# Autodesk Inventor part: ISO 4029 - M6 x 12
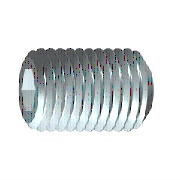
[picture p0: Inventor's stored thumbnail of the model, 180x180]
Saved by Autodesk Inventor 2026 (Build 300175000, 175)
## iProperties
IsCustomPart: 1
Created: 2021-02
Part Number: ISO 4029 - M6 x 12
Material: Stainless Steel, 440C
Description: Hexagon socket set screw with cup point
Document SubType Name: Modeling
Standard: ISO 4029
Designer: Lars Bertram Pedersen
Standard Revision: Third edition 2003-12-01
Standards Organization: ISO
Language: en-US
Size Designation: M6 x 12
Categories: <MemberInstance><Categories><Category DisplayName="Fasteners" InternalName="e4da775c-781d-43d5-af7c-5136215cf5a6" Mnemonic="FSTN"><Category DisplayName="Bolts"
Density: 7.75 g/cm^3
Appearance: Semi-Polished
Author: Lars Bertram Pedersen
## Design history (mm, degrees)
revolve "Body" stored, may be unused: angle "d6" = 90 deg
sketch "Sketch2"
  geometry: L1 (1.732, 0)-(0.866, -1.5); L2 (0.866, -1.5)-(-0.866, -1.5); L3 (-0.866, -1.5)-(-1.732, 0); L4 (-1.732, 0)-(-0.866, 1.5); L5 (-0.866, 1.5)-(0.866, 1.5); L6 (0.866, 1.5)-(1.732, 0); C1 r 3 at (0, 0) reference; A1 r 1.732 centre (0, 0) between (1.732, 0) and (0.866, -1.5) reference; 1 further point
  constraints: 12 end point, 2 point on circle, 1 coincident, 1 horizontal, 11 other
extrude "Slot" join sketch "Sketch2" distance "d8" = 3.5 (= INTI); taper "d9" = 0 deg
workaxis "Work Axis1"
workplane "Work Plane1"
body "Solid1"
chamfer "Chamfer1" distance "d10" = 1.5 (= -0.5 x SPD + 0.5 x NND); stored, may be unused: angle "d11" = 45 deg (= FAWI), second distance "d33" = 1.5 (= -0.5 x SPD + 0.5 x NND)
feature "Thread" dims "d14" = 12 (= NLG), "d15" = 0
chamfer "Chamfer2" distance "d12" = 0.61345 (= -0.5 x GD1 + 0.5 x NND); stored, may be unused: angle "d13" = 45 deg (= FAWI), second distance "d34" = 0.61345 (= -0.5 x GD1 + 0.5 x NND)
sketch "Sketch1"
  geometry: L1 (0.866, 0)-(7.5, 0); L2 (12, 1.732)-(12, 3); L3 (12, 3)-(0, 3); L4 (12, 1.732)-(8.5, 1.732); L5 (8.5, 1.732)-(7.5, 0); L6 (0, 1.5)-(0.866, 0); L7 (0, -0.6)-(0, 3.6) reference; L8 (0, 1.5)-(0, 3); 1 further point
  constraints: 14 end point, 2 parallel, 2 perpendicular, 1 horizontal, 1 midpoint, 1 point on line
  dimensions: "d0" = 3.5 distance of L2.start L4.end (= INTI); "d1" = 60 deg angle of L5 L1; "d2" = 6 diameter of L3 L1 (= NND); "d3" = 3.4641 diameter of L4 L1 (= 1.1547 x SW); "d4" = 12 distance from line of L2 L6.start (= NLG); "d5" = 60 deg angle of L1 L6 (= 0.5 x ANG); "d7" = 3 diameter of L6.start L1 (= SPD)
other parameters: "NND" = 6 [user parameter; used in 5 equation terms], "NLG" = 12 [user parameter; used in 2 equation terms], "INTI" = 3.5 [user parameter; used in 2 equation terms], "FAWI" = 45 deg [user parameter; used in 2 equation terms], "SW" = 3 [user parameter; used in 2 equation terms], "GD1" = 4.7731 (= THREADDIA - 1.2269 x PTC) [user parameter; used in 2 equation terms], "ANG" = 120 deg [user parameter; used in 1 equation term], "FAWI1" = 45 deg [user parameter], "SPD" = 3 [user parameter; used in 3 equation terms], "d16" = 0, "d35" = 0, "d37" = 0, "GUL" = 0.61345 (= 0.61345 x PTC) [user parameter], "TOA" = 30 deg [user parameter], "THREADDIA" = 6 [user parameter; used in 1 equation term], "PTC" = 1 [user parameter; used in 4 equation terms], "GAL" = 0.61345 (= 0.61345 x PTC) [user parameter], "E0" = 3.465 (= 1.155 x SW) [user parameter]
